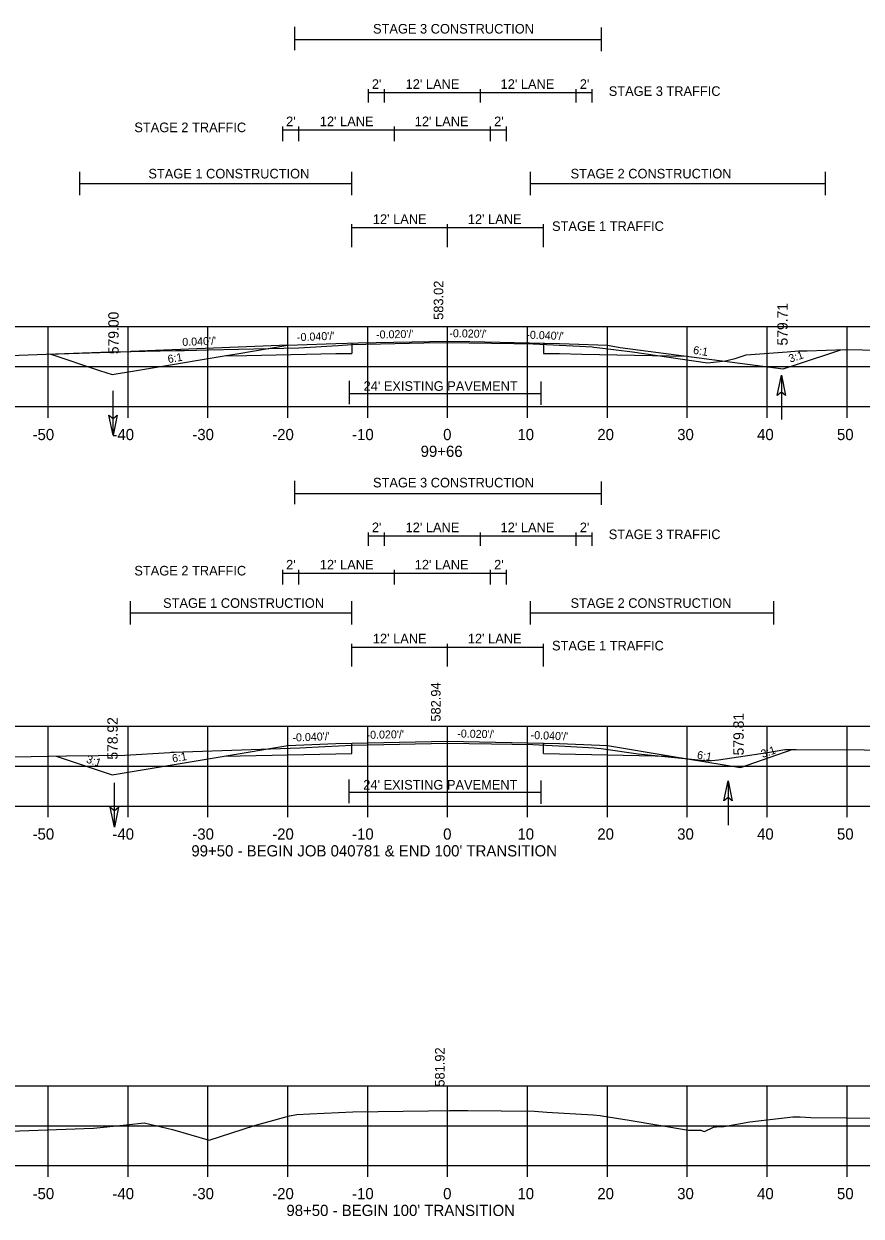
# Model space of a CAD drawing. Extents: x 642114 to 642416, y 286928 to 293347.
# Drawn here: x 642207.2 to 642312, y 286934.1 to 287083.3 of the extents above; entities that cross this region are included whole.
import ezdxf

# ---------------------------------------------------------------- set-up
doc = ezdxf.new("R2010")
doc.units = 0
for name, color, linetype in [('59', 7, 'Continuous'), ('Level 43', 7, 'Continuous'), ('Level 58', 7, 'Continuous'), ('R_Axis', 7, 'Continuous'), ('R_Axis Annot', 7, 'Continuous'), ('R_Drive', 7, 'Continuous'), ('R_Exist Surface', 7, 'Continuous'), ('R_Exist Surface Annot', 7, 'Continuous'), ('R_Fin Surface', 7, 'Continuous'), ('R_Grid', 7, 'Continuous'), ('R_Xsect Elev', 7, 'Continuous'), ('R_Xsect Slope', 7, 'Continuous')]:
    doc.layers.add(name, color=color, linetype=linetype)

# ---------------------------------------------------------------- blocks, each defined once
blk = doc.blocks.new('FA')
at = {"layer": 'Level 43'}
blk.add_lwpolyline([(7.94, 0), (0, 0)], dxfattribs=at)
at = {"layer": 'Level 58'}
blk.add_lwpolyline([(4.34, 0.75), (7.94, 0), (4.34, -0.75), (4.94, 0)], close=True, dxfattribs=at)

msp = doc.modelspace()

# ---------------------------------------------------------------- linework, layer by layer
at = {"layer": 'R_Axis'}
for p, q in [((642120.24, 287035.39), (642400.24, 287035.39)), ((642210.24, 287033.99), (642210.24, 287035.39)), ((642220.24, 287033.99), (642220.24, 287035.39)), ((642230.24, 287033.99), (642230.24, 287035.39)), ((642240.24, 287033.99), (642240.24, 287035.39)), ((642250.24, 287033.99), (642250.24, 287035.39)), ((642260.24, 287033.99), (642260.24, 287035.39)), ((642270.24, 287033.99), (642270.24, 287035.39)), ((642280.24, 287033.99), (642280.24, 287035.39)), ((642290.24, 287033.99), (642290.24, 287035.39)), ((642300.24, 287033.99), (642300.24, 287035.39)), ((642310.24, 287033.99), (642310.24, 287035.39)), ((642120.24, 286985.39), (642400.24, 286985.39)), ((642210.24, 286983.99), (642210.24, 286985.39)), ((642220.24, 286983.99), (642220.24, 286985.39)), ((642230.24, 286983.99), (642230.24, 286985.39)), ((642240.24, 286983.99), (642240.24, 286985.39)), ((642250.24, 286983.99), (642250.24, 286985.39)), ((642260.24, 286983.99), (642260.24, 286985.39)), ((642270.24, 286983.99), (642270.24, 286985.39)), ((642280.24, 286983.99), (642280.24, 286985.39)), ((642290.24, 286983.99), (642290.24, 286985.39)), ((642300.24, 286983.99), (642300.24, 286985.39)), ((642310.24, 286983.99), (642310.24, 286985.39)), ((642120.24, 286940.39), (642400.24, 286940.39)), ((642210.24, 286938.99), (642210.24, 286940.39)), ((642220.24, 286938.99), (642220.24, 286940.39)), ((642230.24, 286938.99), (642230.24, 286940.39)), ((642240.24, 286938.99), (642240.24, 286940.39)), ((642250.24, 286938.99), (642250.24, 286940.39)), ((642260.24, 286938.99), (642260.24, 286940.39)), ((642270.24, 286938.99), (642270.24, 286940.39)), ((642280.24, 286938.99), (642280.24, 286940.39)), ((642290.24, 286938.99), (642290.24, 286940.39)), ((642300.24, 286938.99), (642300.24, 286940.39)), ((642310.24, 286938.99), (642310.24, 286940.39))]:
    msp.add_line(p, q, dxfattribs=at)
at = {"layer": 'R_Drive'}
msp.add_line((642210.24, 287041.95), (642220.6, 287042.27), dxfattribs=at)
msp.add_lwpolyline([(642240.24, 287043.06), (642220.6, 287042.27)], dxfattribs=at)
at = {"layer": 'R_Exist Surface'}
for p, q in [((642248.24, 286991.97), (642248.24, 286993.26)), ((642272.24, 286991.97), (642272.24, 286993.26))]:
    msp.add_line(p, q, dxfattribs=at)
for points in [[(642248.24, 287043.34), (642248.24, 287042.05)], [(642272.24, 287043.34), (642272.24, 287042.05)], [(642232.25, 287041.73), (642235.05, 287041.78), (642246.24, 287042.01), (642248.24, 287042.05)], [(642272.24, 287042.05), (642274.24, 287042.01), (642277.04, 287041.95), (642290.22, 287041.69)], [(642232.25, 286991.65), (642246.24, 286991.93), (642248.24, 286991.97)], [(642272.24, 286991.97), (642274.24, 286991.93), (642288.23, 286991.65)]]:
    msp.add_lwpolyline(points, dxfattribs=at)
at = {"layer": 'R_Exist Surface Annot'}
for points in [[(642203.15, 287041.69), (642217.97, 287042.23), (642218.58, 287042.22), (642226.16, 287042.42), (642227.28, 287042.4), (642230.29, 287042.49), (642241.62, 287042.76), (642246.52, 287043.05), (642248.21, 287043.15), (642257.26, 287043.35), (642260.15, 287043.41), (642268.53, 287043.28), (642270.95, 287043.24), (642276.76, 287042.95), (642278.34, 287042.87), (642278.53, 287042.84), (642279.28, 287042.76), (642283.39, 287042.24), (642292.79, 287040.85), (642295.02, 287041.1), (642295.71, 287041.28), (642296.24, 287041.42), (642297.62, 287041.87), (642302.75, 287042.25), (642304.16, 287042.35), (642305.26, 287042.35), (642310.02, 287042.53), (642316.52, 287042.39)], [(642199.22, 286991.44), (642212.52, 286991.67), (642216.51, 286991.73), (642219.82, 286991.78), (642225.48, 286992.09), (642225.63, 286992.13), (642226.03, 286992.12), (642227.12, 286992.16), (642241.72, 286992.66), (642244.86, 286992.84), (642248.28, 286993.03), (642254.22, 286993.15), (642260.15, 286993.28), (642265.74, 286993.19), (642270.92, 286993.11), (642274.96, 286992.9), (642278.57, 286992.7), (642278.98, 286992.64), (642279.47, 286992.58), (642284.1, 286991.93), (642292.87, 286991.06), (642294.14, 286991.16), (642300.29, 286992.11), (642302.45, 286992.48), (642303.86, 286992.47), (642320.98, 286992.39)], [(642201.89, 286944.58), (642207.8, 286944.8), (642215.91, 286945.1), (642220.04, 286945.5), (642222.25, 286945.75), (642225.81, 286944.91), (642230.4, 286943.59), (642236.07, 286945.43), (642240.46, 286946.64), (642241.16, 286946.76), (642241.37, 286946.8), (642242.98, 286946.87), (642248.37, 286947.12), (642257.84, 286947.27), (642260.47, 286947.31), (642262.78, 286947.28), (642271.12, 286947.19), (642272.64, 286947.1), (642278.46, 286946.76), (642279.32, 286946.65), (642279.53, 286946.63), (642282.98, 286946.1), (642290.38, 286944.85), (642291.93, 286944.84), (642292.25, 286944.72), (642292.39, 286944.67), (642293.53, 286945.19), (642293.89, 286945.24), (642294.82, 286945.28), (642298.09, 286945.87), (642303.44, 286946.5), (642304.36, 286946.52), (642305.71, 286946.4), (642314.87, 286946.34)]]:
    msp.add_lwpolyline(points, dxfattribs=at)
at = {"layer": 'R_Fin Surface'}
for points in [[(642224.05, 287040.36), (642232.25, 287041.73), (642233.85, 287041.99), (642240.24, 287043.06), (642241.44, 287043.11), (642246.24, 287043.3), (642249.04, 287043.36), (642260.24, 287043.58), (642263.04, 287043.52), (642274.24, 287043.3), (642275.44, 287043.25), (642280.24, 287043.06), (642281.84, 287042.79), (642302.24, 287040.1)], [(642210.44, 287041.99), (642216.68, 287039.91), (642218.24, 287039.39), (642221.04, 287039.86), (642224.05, 287040.36)], [(642302.24, 287040.1), (642304.05, 287040.7), (642309.46, 287042.51)], [(642218.24, 286989.31), (642232.25, 286991.65), (642240.24, 286992.98), (642246.24, 286993.22), (642260.24, 286993.5), (642274.24, 286993.22), (642280.24, 286992.98), (642288.23, 286991.65), (642296.91, 286990.2)], [(642296.91, 286990.2), (642303.38, 286992.47)], [(642211.23, 286991.65), (642218.24, 286989.31)]]:
    msp.add_lwpolyline(points, dxfattribs=at)
at = {"layer": 'R_Grid'}
for p, q in [((642120.24, 287045.39), (642400.24, 287045.39)), ((642210.24, 287035.39), (642210.24, 287045.39)), ((642220.24, 287035.39), (642220.24, 287045.39)), ((642230.24, 287035.39), (642230.24, 287045.39)), ((642240.24, 287035.39), (642240.24, 287045.39)), ((642250.24, 287035.39), (642250.24, 287045.39)), ((642260.24, 287035.39), (642260.24, 287045.39)), ((642270.24, 287035.39), (642270.24, 287045.39)), ((642280.24, 287035.39), (642280.24, 287045.39)), ((642290.24, 287035.39), (642290.24, 287045.39)), ((642300.24, 287035.39), (642300.24, 287045.39)), ((642310.24, 287035.39), (642310.24, 287045.39)), ((642120.24, 287040.39), (642400.24, 287040.39)), ((642120.24, 287035.39), (642400.24, 287035.39)), ((642120.24, 286995.39), (642400.24, 286995.39)), ((642210.24, 286985.39), (642210.24, 286995.39)), ((642220.24, 286985.39), (642220.24, 286995.39)), ((642230.24, 286985.39), (642230.24, 286995.39)), ((642240.24, 286985.39), (642240.24, 286995.39)), ((642250.24, 286985.39), (642250.24, 286995.39)), ((642260.24, 286985.39), (642260.24, 286995.39)), ((642270.24, 286985.39), (642270.24, 286995.39)), ((642280.24, 286985.39), (642280.24, 286995.39)), ((642290.24, 286985.39), (642290.24, 286995.39)), ((642300.24, 286985.39), (642300.24, 286995.39)), ((642310.24, 286985.39), (642310.24, 286995.39)), ((642120.24, 286990.39), (642400.24, 286990.39)), ((642120.24, 286985.39), (642400.24, 286985.39)), ((642120.24, 286950.39), (642400.24, 286950.39)), ((642210.24, 286940.39), (642210.24, 286950.39)), ((642220.24, 286940.39), (642220.24, 286950.39)), ((642230.24, 286940.39), (642230.24, 286950.39)), ((642240.24, 286940.39), (642240.24, 286950.39)), ((642250.24, 286940.39), (642250.24, 286950.39)), ((642260.24, 286940.39), (642260.24, 286950.39)), ((642270.24, 286940.39), (642270.24, 286950.39)), ((642280.24, 286940.39), (642280.24, 286950.39)), ((642290.24, 286940.39), (642290.24, 286950.39)), ((642300.24, 286940.39), (642300.24, 286950.39)), ((642310.24, 286940.39), (642310.24, 286950.39)), ((642120.24, 286945.39), (642400.24, 286945.39)), ((642120.24, 286940.39), (642400.24, 286940.39))]:
    msp.add_line(p, q, dxfattribs=at)
at = {"layer": 'R_Xsect Elev'}
for p, q in [((642241.12, 287079.98), (642241.12, 287082.91)), ((642279.5, 287079.88), (642279.5, 287082.81)), ((642241.12, 287081.32), (642279.5, 287081.32)), ((642250.34, 287073.45), (642250.34, 287075.11)), ((642250.34, 287074.69), (642278.34, 287074.69)), ((642252.34, 287073.45), (642252.34, 287075.11)), ((642264.34, 287073.45), (642264.34, 287075.11)), ((642276.34, 287073.45), (642276.34, 287075.11)), ((642278.34, 287073.45), (642278.34, 287075.11)), ((642239.6, 287068.61), (642239.6, 287070.44)), ((642239.6, 287070.02), (642267.6, 287070.02)), ((642241.6, 287068.61), (642241.6, 287070.44)), ((642253.6, 287068.61), (642253.6, 287070.44)), ((642265.6, 287068.61), (642265.6, 287070.44)), ((642267.6, 287068.61), (642267.6, 287070.44)), ((642214.19, 287061.86), (642214.19, 287064.78)), ((642248.23, 287061.86), (642248.23, 287064.78)), ((642270.63, 287061.86), (642270.63, 287064.78)), ((642307.55, 287061.86), (642307.55, 287064.78)), ((642214.19, 287063.32), (642248.23, 287063.32)), ((642270.63, 287063.32), (642307.55, 287063.32)), ((642248.24, 287055.33), (642248.24, 287058.21)), ((642260.24, 287055.33), (642260.24, 287058.21)), ((642272.24, 287055.33), (642272.24, 287058.21)), ((642248.24, 287057.79), (642272.24, 287057.79)), ((642247.97, 287035.68), (642247.97, 287038.6)), ((642271.97, 287035.59), (642271.97, 287038.51)), ((642247.97, 287037.03), (642271.97, 287037.03)), ((642241.12, 287023.18), (642241.12, 287026.11)), ((642279.5, 287023.08), (642279.5, 287026.01)), ((642241.12, 287024.52), (642279.5, 287024.52)), ((642250.34, 287017.97), (642250.34, 287019.63)), ((642250.34, 287019.21), (642278.34, 287019.21)), ((642252.34, 287017.97), (642252.34, 287019.63)), ((642264.34, 287017.97), (642264.34, 287019.63)), ((642276.34, 287017.97), (642276.34, 287019.63)), ((642278.34, 287017.97), (642278.34, 287019.63)), ((642239.6, 287013.14), (642239.6, 287014.96)), ((642241.6, 287013.14), (642241.6, 287014.96)), ((642253.6, 287013.14), (642253.6, 287014.96)), ((642265.6, 287013.14), (642265.6, 287014.96)), ((642267.6, 287013.14), (642267.6, 287014.96)), ((642239.6, 287014.55), (642267.6, 287014.55)), ((642220.54, 287008.12), (642220.54, 287011.04)), ((642248.23, 287008.12), (642248.23, 287011.04)), ((642270.63, 287008.12), (642270.63, 287011.04)), ((642301.08, 287008.12), (642301.08, 287011.04)), ((642220.54, 287009.58), (642248.23, 287009.58)), ((642270.63, 287009.58), (642301.08, 287009.58)), ((642248.24, 287002.84), (642248.24, 287005.71)), ((642260.24, 287002.84), (642260.24, 287005.71)), ((642272.24, 287002.84), (642272.24, 287005.71)), ((642248.24, 287005.29), (642272.24, 287005.29)), ((642247.93, 286985.77), (642247.93, 286988.7)), ((642271.93, 286985.69), (642271.93, 286988.61)), ((642247.93, 286987.12), (642271.93, 286987.12))]:
    msp.add_line(p, q, dxfattribs=at)

# ---------------------------------------------------------------- block references
at = {"layer": 'R_Xsect Elev', "xscale": 0.7, "yscale": 0.7}
for p, rotation in [((642302.03, 287033.75), 90), ((642218.35, 287037.35), -90.00000000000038), ((642218.53, 286988.29), -90.00000000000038), ((642295.35, 286982.99), 90)]:
    msp.add_blockref('FA', p, dxfattribs=dict(at, rotation=rotation))

# ---------------------------------------------------------------- texts
at = {"layer": '59'}
msp.add_text(' 579.81', height=1.3, rotation=90, dxfattribs=at).set_placement((642297.31, 286991.25))
at = {"layer": 'R_Axis Annot'}
for s, p in [('-50', (642208.28, 287031.19)), ('-40', (642218.28, 287031.19)), ('-30', (642228.28, 287031.19)), ('-20', (642238.28, 287031.19)), ('-10', (642248.28, 287031.19)), ('0', (642259.68, 287031.19)), ('10', (642268.98, 287031.19)), ('20', (642278.98, 287031.19)), ('30', (642288.98, 287031.19)), ('40', (642298.98, 287031.19)), ('50', (642308.98, 287031.19)), ('99+66', (642256.86, 287029.09)), ('-50', (642208.28, 286981.19)), ('-40', (642218.28, 286981.19)), ('-30', (642228.28, 286981.19)), ('-20', (642238.28, 286981.19)), ('-10', (642248.28, 286981.19)), ('0', (642259.68, 286981.19)), ('10', (642268.98, 286981.19)), ('20', (642278.98, 286981.19)), ('30', (642288.98, 286981.19)), ('40', (642298.98, 286981.19)), ('50', (642308.98, 286981.19)), ("99+50 - BEGIN JOB 040781 & END 100' TRANSITION", (642228.16, 286979.09)), ('-50', (642208.28, 286936.19)), ('-40', (642218.28, 286936.19)), ('-30', (642228.28, 286936.19)), ('-20', (642238.28, 286936.19)), ('-10', (642248.28, 286936.19)), ('0', (642259.68, 286936.19)), ('10', (642268.98, 286936.19)), ('20', (642278.98, 286936.19)), ('30', (642288.98, 286936.19)), ('40', (642298.98, 286936.19)), ('50', (642308.98, 286936.19)), ("98+50 - BEGIN 100' TRANSITION", (642240.06, 286934.09))]:
    msp.add_text(s, height=1.4, dxfattribs=at).set_placement(p)
at = {"layer": 'R_Xsect Elev'}
for s, p in [('STAGE 3 CONSTRUCTION', (642250.9, 287082.07)), ("2'", (642250.76, 287075.15)), ("12' LANE", (642254.98, 287075.15)), ("12' LANE", (642266.87, 287075.15)), ("2'", (642276.79, 287075.15)), ('STAGE 3 TRAFFIC', (642280.41, 287074.27)), ("2'", (642240.02, 287070.48)), ("12' LANE", (642244.24, 287070.48)), ("12' LANE", (642256.13, 287070.48)), ("2'", (642266.06, 287070.48)), ('STAGE 2 TRAFFIC', (642221.02, 287069.73)), ('STAGE 1 CONSTRUCTION', (642222.78, 287063.94)), ('STAGE 2 CONSTRUCTION', (642275.63, 287063.94)), ("12' LANE", (642250.88, 287058.25)), ("12' LANE", (642262.77, 287058.25)), ('STAGE 1 TRAFFIC', (642273.31, 287057.37)), ("24' EXISTING PAVEMENT", (642249.72, 287037.36)), ('STAGE 3 CONSTRUCTION', (642250.9, 287025.27)), ("2'", (642250.76, 287019.67)), ("12' LANE", (642254.98, 287019.67)), ("12' LANE", (642266.87, 287019.67)), ("2'", (642276.79, 287019.67)), ('STAGE 3 TRAFFIC', (642280.41, 287018.8)), ("2'", (642240.02, 287015)), ("12' LANE", (642244.24, 287015)), ("12' LANE", (642256.13, 287015)), ("2'", (642266.06, 287015)), ('STAGE 2 TRAFFIC', (642221.02, 287014.25)), ('STAGE 1 CONSTRUCTION', (642224.62, 287010.2)), ('STAGE 2 CONSTRUCTION', (642275.63, 287010.2)), ("12' LANE", (642250.88, 287005.75)), ("12' LANE", (642262.77, 287005.75)), ('STAGE 1 TRAFFIC', (642273.31, 287004.87)), ("24' EXISTING PAVEMENT", (642249.68, 286987.46))]:
    msp.add_text(s, height=1.2, dxfattribs=at).set_placement(p)
for s, height, p in [('583.02', 1.2, (642259.7, 287046.24)), (' 579.71', 1.3, (642302.81, 287042.55)), (' 579.00', 1.3, (642219.06, 287041.46)), ('582.94', 1.2, (642259.36, 286995.96)), (' 578.92', 1.3, (642218.94, 286990.72)), ('581.92', 1.2, (642259.86, 286950.28))]:
    msp.add_text(s, height=height, rotation=90, dxfattribs=at).set_placement(p)
at = {"layer": 'R_Xsect Slope'}
for s, rotation, p in [("-0.040'/'", 2.2906, (642241.4, 287043.57)), ("-0.020'/'", 1.1458, (642251.29, 287043.9)), ("-0.020'/'", 358.8542, (642260.45, 287044.08)), ("-0.040'/'", 357.7094, (642270.08, 287043.9)), ("0.040'/'", 2.1943, (642227.04, 287042.97)), ('6:1', 350.5358, (642290.92, 287042.01)), ('6:1', 9.4642, (642225.28, 287040.83)), ('3:1', 18.4332, (642303.13, 287040.87)), ("-0.040'/'", 2.2906, (642240.83, 286993.46)), ("-0.020'/'", 1.1458, (642250.1, 286993.8)), ("-0.020'/'", 358.8542, (642261.44, 286993.98)), ("-0.040'/'", 357.7094, (642270.62, 286993.8)), ('6:1', 350.5358, (642291.41, 286991.34)), ('3:1', 19.3526, (642299.66, 286991.4)), ('3:1', 341.5668, (642214.92, 286990.86)), ('6:1', 9.4642, (642225.83, 286990.85)), ('6:1', 9.4642, (642225.83, 286990.85))]:
    msp.add_text(s, height=1, rotation=rotation, dxfattribs=at).set_placement(p)

doc.saveas('drawing.dxf')
